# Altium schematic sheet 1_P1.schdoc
size 431 x 309 mm; Symbol: Sheet-Symbol_A4; Device: Sheet-Symbol_A4; Company: 嘉立创EDA; Version: V1.0; Page Size: A4; @Project Name: New Project_2023-10-27_14-14-08; @Page Count: 1; @Update Date: 2023-11-15; @Create Date: 2023-10-27; @Schematic Name: NODEMCU_BOARD; @Page No: 1; @Page Name: P1
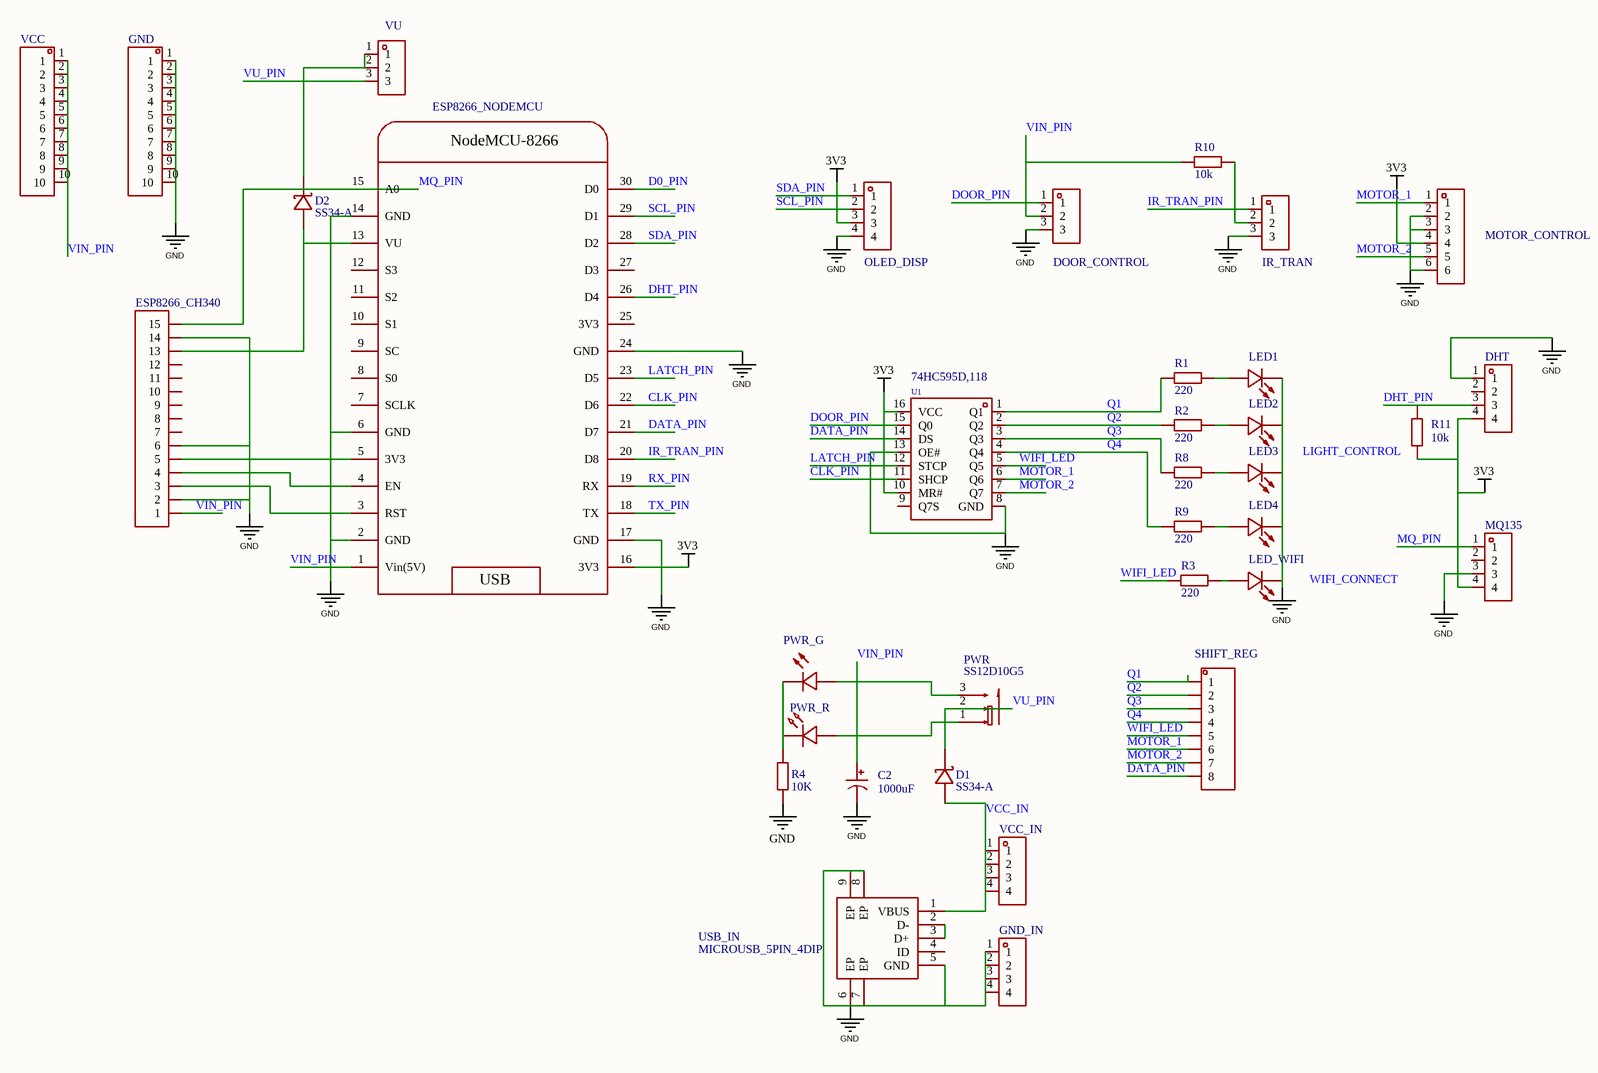
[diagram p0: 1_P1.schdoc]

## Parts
C2  1000uF  [CAP-TH_BD8.0-P3.50-D0.6-FD]  (value not drawn)
D1  SS34-A  [SMA_L4.3-W2.6-LS5.2-RD]  (value not drawn)
D2  SS34-A  [SMA_L4.3-W2.6-LS5.2-RD]  (value not drawn)
DHT  HDR-F_2.54_1x4P  [HDR-TH_4P-P2.54-V-F]  (value not drawn)
DOOR_CONTROL  HDR-F_2.54_1x3P  [HDR-TH_3P-P2.54-V-F]  (value not drawn)
ESP8266_CH340  HDR-F_2.54_1x15P  [HDR-TH_15P-P2.54-V-F-1]  (value not drawn)
ESP8266_NODEMCU  NodeMCU8266  [NODEMCU8266]  (value not drawn)
GND  HDR-M_2.54_1x10P  [HDR-TH_10P-P2.54-V-M-1]  (value not drawn)
GND_IN  HDR-M_2.54_1x4P  [HDR-TH_4P-P2.54-V-M]  (value not drawn)
IR_TRAN  HDR-F_2.54_1x3P  [HDR-TH_3P-P2.54-V-F]  (value not drawn)
LED1  LTST-C171KFKT  [LED-TH_BD5.8-P2.54-RD]  (value not drawn)
LED2  LTST-C171KFKT  [LED-TH_BD5.8-P2.54-RD]  (value not drawn)
LED3  LTST-C171KFKT  [LED-TH_BD5.8-P2.54-RD]  (value not drawn)
LED4  LTST-C171KFKT  [LED-TH_BD5.8-P2.54-RD]  (value not drawn)
LED_WIFI  LTST-C171KFKT  [LED0805-RD_ORANGE]  (value not drawn)
MOTOR_CONTROL  HDR-F_2.54_1x6P  [HDR-TH_6P-P2.54-V-F]  (value not drawn)
MQ135  HDR-M_2.54_1x4P  [HDR-TH_4P-P2.54-V-M]  (value not drawn)
OLED_DISP  HDR-F_2.54_1x4P  [HDR-TH_4P-P2.54-V-F]  (value not drawn)
PWR  SS12D10G5  [SS12D10G5]  (value not drawn)
PWR_G  LTST-C170GKT  [LED0805-RD_GREEN]  (value not drawn)
PWR_R  HL-PSC-2012S9AC-CZ  [LED0805-RD_RED]  (value not drawn)
R1  220  [R0603]  (value not drawn)
R2  220  [R0603]  (value not drawn)
R3  220  [R0603]  (value not drawn)
R4  10K  [R1206]  (value not drawn)
R8  220  [R0603]  (value not drawn)
R9  220  [R0603]  (value not drawn)
R10  10k  [R0603]  (value not drawn)
R11  10k  [R0603]  (value not drawn)
SHIFT_REG  HDR-M_2.54_1x8P  [HDR-TH_8P-P2.54-V-M]  (value not drawn)
U1  74HC595D,118  [CDIP-16_L19.7-W6.6-P2.54-LS7.6-BL]  (value not drawn)
USB_IN  MICROUSB_5PIN_4DIP  [MICRO-USB-SMD_U254-051N-4BH806]  (value not drawn)
VCC  HDR-M_2.54_1x10P  [HDR-TH_10P-P2.54-V-M-1]  (value not drawn)
VCC_IN  HDR-M_2.54_1x4P  [HDR-TH_4P-P2.54-V-M]  (value not drawn)
VU  HDR-M_2.54_1x3P  [HDR-TH_3P-P2.54-V-M]  (value not drawn)

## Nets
3V3: DHT.4 ESP8266_NODEMCU.16(3V3) MOTOR_CONTROL.4 MQ135.4 OLED_DISP.3 R11.1 U1.10(MR#) U1.16(VCC)
GND: C2.2 DHT.1 DOOR_CONTROL.3 ESP8266_CH340.2 ESP8266_CH340.6 ESP8266_CH340.14 ESP8266_NODEMCU.2(GND) ESP8266_NODEMCU.6(GND) ESP8266_NODEMCU.14(GND) ESP8266_NODEMCU.17(GND) ESP8266_NODEMCU.24(GND) GND.1 GND.2 GND.3 GND.4 GND.5 GND.6 GND.7 GND.8 GND.9 GND.10 GND_IN.1 GND_IN.2 GND_IN.3 GND_IN.4 IR_TRAN.3 LED1.1(C) LED2.1(C) LED3.1(C) LED4.1(C) LED_WIFI.1(C) MOTOR_CONTROL.2 MOTOR_CONTROL.3 MOTOR_CONTROL.6 MQ135.3 OLED_DISP.4 R4.1 U1.8(GND) U1.13(OE#) USB_IN.5(GND) USB_IN.6(EP) USB_IN.7(EP) USB_IN.8(EP) USB_IN.9(EP)
CLK_PIN: ESP8266_NODEMCU.22(D6) U1.11(SHCP)
D0_PIN: ESP8266_NODEMCU.30(D0)
DATA_PIN: ESP8266_NODEMCU.21(D7) SHIFT_REG.8 U1.14(DS)
DHT_PIN: DHT.3 ESP8266_NODEMCU.26(D4) R11.2
DOOR_PIN: DOOR_CONTROL.1 U1.15(Q0)
IR_TRAN_PIN: ESP8266_NODEMCU.20(D8) IR_TRAN.1
LATCH_PIN: ESP8266_NODEMCU.23(D5) U1.12(STCP)
MOTOR_1: MOTOR_CONTROL.1 SHIFT_REG.6 U1.6(Q6)
MOTOR_2: MOTOR_CONTROL.5 SHIFT_REG.7 U1.7(Q7)
MQ_PIN: ESP8266_CH340.15 ESP8266_NODEMCU.15(A0) MQ135.1
Q1: R1.1 SHIFT_REG.1 U1.1(Q1)
Q2: R2.1 SHIFT_REG.2 U1.2(Q2)
Q3: R8.1 SHIFT_REG.3 U1.3(Q3)
Q4: R9.1 SHIFT_REG.4 U1.4(Q4)
RX_PIN: ESP8266_NODEMCU.19(RX)
SCL_PIN: ESP8266_NODEMCU.29(D1) OLED_DISP.2
SDA_PIN: ESP8266_NODEMCU.28(D2) OLED_DISP.1
TX_PIN: ESP8266_NODEMCU.18(TX)
VCC_IN: D1.2(A) USB_IN.1(VBUS) VCC_IN.1 VCC_IN.2 VCC_IN.3 VCC_IN.4
VIN_PIN: C2.1 DOOR_CONTROL.2 ESP8266_CH340.1 ESP8266_NODEMCU.1(Vin(5V)) PWR.3 PWR_G.2(+) R10.1 VCC.1 VCC.2 VCC.3 VCC.4 VCC.5 VCC.6 VCC.7 VCC.8 VCC.9 VCC.10
VU_PIN: D1.1(C) PWR.2 VU.3
WIFI_LED: R3.1 SHIFT_REG.5 U1.5(Q5)
NetD2_1: D2.1(C) VU.1 VU.2
NetD2_2: D2.2(A) ESP8266_CH340.13 ESP8266_NODEMCU.13(VU)
NetESP8266_CH340_3: ESP8266_CH340.3 ESP8266_NODEMCU.3(RST)
NetESP8266_CH340_4: ESP8266_CH340.4 ESP8266_NODEMCU.4(EN)
NetESP8266_CH340_5: ESP8266_CH340.5 ESP8266_NODEMCU.5(3V3)
NetIR_TRAN_2: IR_TRAN.2 R10.2
NetLED1_2: LED1.2(A) R1.2
NetLED2_2: LED2.2(A) R2.2
NetLED3_2: LED3.2(A) R8.2
NetLED4_2: LED4.2(A) R9.2
NetLED_WIFI_2: LED_WIFI.2(A) R3.2
NetPWR_1: PWR.1 PWR_R.2(+)
NetPWR_G_1: PWR_G.1(-) PWR_R.1(-) R4.2
NetUSB_IN_2: USB_IN.2(D-) USB_IN.3(D+)

Not connected (* = marked no-connect by the designer): DHT 2; ESP8266_CH340 7 8 9 10 11 12; ESP8266_NODEMCU 7(SCLK) 8(S0) 9(SC) 10(S1) 11(S2) 12(S3) 25(3V3) 27(D3); MQ135 2; U1 9(Q7S); USB_IN 4(ID)

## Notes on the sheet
- LIGHT_CONTROL
- WIFI_CONNECT

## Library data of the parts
C2 = 1000uF: Manufacturer: ValuePro; Manufacturer Part: 1000uF 16Vblack gold 8*20; Convert to PCB: yes
D1 D2 = SS34-A: Manufacturer: Formosa Microsemi; Convert to PCB: yes
DHT OLED_DISP = HDR-F_2.54_1x4P: Manufacturer: BOOMELE(博穆精密); Symbol: 2.54-1*4P母; Convert to PCB: yes
DOOR_CONTROL IR_TRAN = HDR-F_2.54_1x3P: Manufacturer: XFCN(兴飞); Symbol: PM254V-11-03-H85; Convert to PCB: yes
ESP8266_CH340 = HDR-F_2.54_1x15P: Convert to PCB: yes
ESP8266_NODEMCU = NodeMCU8266: Convert to PCB: yes
GND VCC = HDR-M_2.54_1x10P: Manufacturer Part: 2.54-1*10P针; Manufacturer: BOOMELE(博穆精密); Symbol: Header-Male-2.54_1x10; Convert to PCB: yes
GND_IN MQ135 VCC_IN = HDR-M_2.54_1x4P: Manufacturer: XFCN(兴飞); Symbol: PZ254V-11-04P; Convert to PCB: yes
LED1-LED4 = LTST-C171KFKT: Manufacturer: Lite-On; Convert to PCB: yes; Origin Footprint: LED0805-RD_ORANGE
LED_WIFI = LTST-C171KFKT: Manufacturer: Lite-On; Convert to PCB: yes
MOTOR_CONTROL = HDR-F_2.54_1x6P: Manufacturer: BOOMELE(博穆精密); Manufacturer Part: 2.54-1*6P母; Symbol: Header-Female-2.54_1x6; Convert to PCB: yes
PWR = SS12D10G5: Convert to PCB: yes
PWR_G = LTST-C170GKT: Manufacturer: Lite-On; Convert to PCB: yes
PWR_R = HL-PSC-2012S9AC-CZ: Manufacturer: HONGLITRONIC(Hongli Zhihui (HONGLITRONIC)); Convert to PCB: yes
R1-R3 R8-R11 = Res_0603: Symbol: 电阻; Convert to PCB: yes
R4 = 10K: Manufacturer: YAGEO; Manufacturer Part: RT1206BRD0710KL; Resistance: 10kΩ; Convert to PCB: yes
SHIFT_REG = HDR-M_2.54_1x8P: Manufacturer: Ckmtw(灿科盟); Manufacturer Part: B-2100S08P-A110; Symbol: Header-Male-2.54_1x8; Convert to PCB: yes
U1 = 74HC595D,118: 每个元件位数:8;功能:串行至并行或串行;电源电压:2V~6V;; Manufacturer: Nexperia(安世); Add into BOM: yes; Number of Bits per Element: 8; Output Type: 三态; Supply Voltage: 2V~6V
USB_IN = MICROUSB_5PIN_4DIP: Manufacturer: null; Convert to PCB: yes
VU = HDR-M_2.54_1x3P: Symbol: PZ254V-11-03P_C2937625; Convert to PCB: yes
